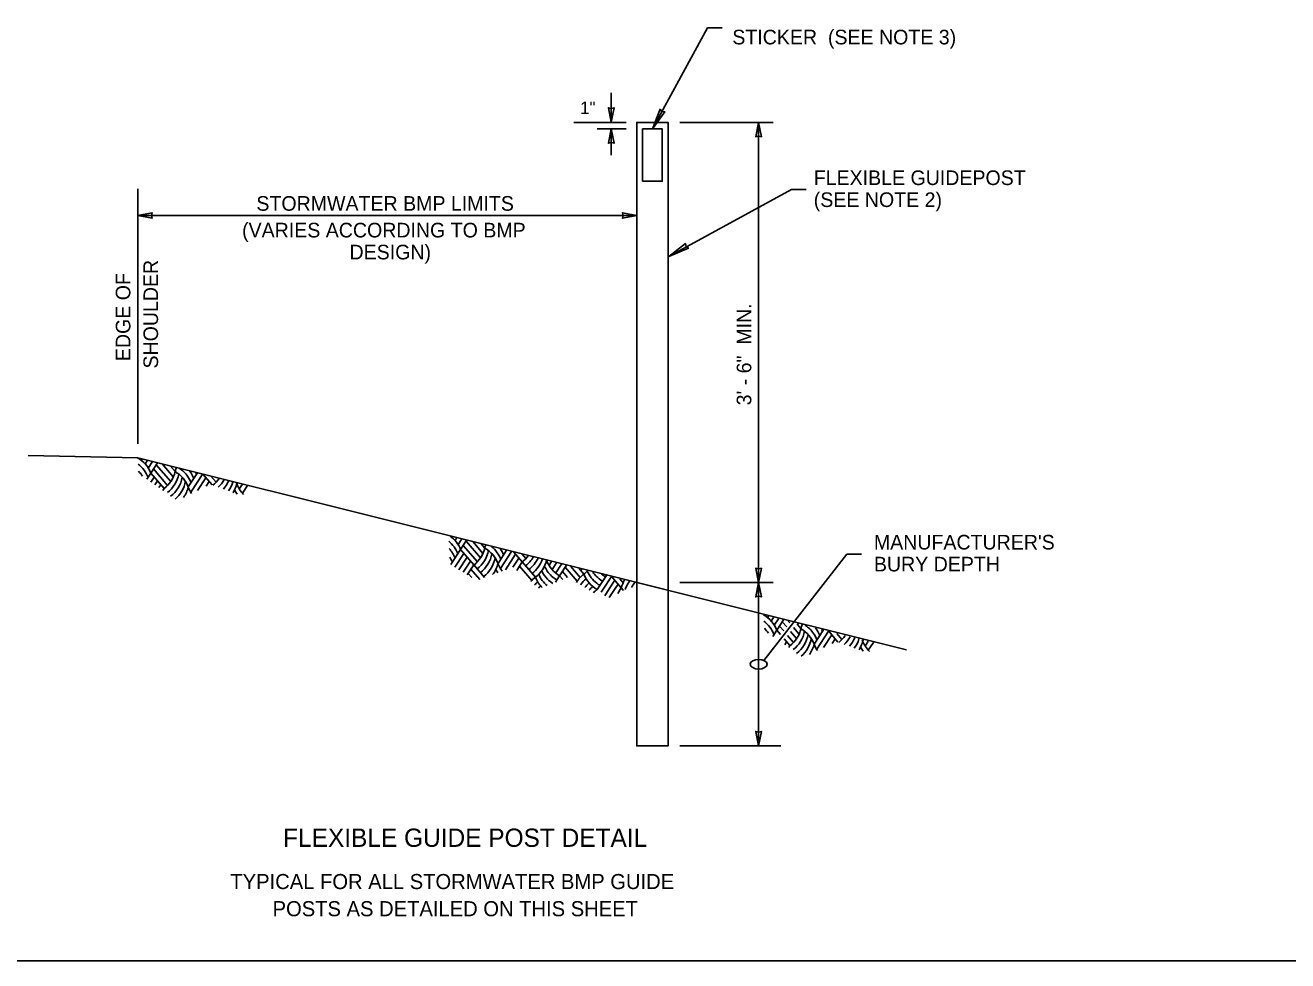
# Model space of a CAD drawing. Extents: x 99862 to 103151, y 100000 to 102076.
# Drawn here: x 101059 to 102440, y 100000 to 101023 of the extents above; entities that cross this region are included whole.
import ezdxf

# ---------------------------------------------------------------- set-up
doc = ezdxf.new("R2010")
doc.units = 0
for name, color, linetype in [('Default', 7, 'Continuous'), ('EV_EC_VegetativeFilterStripNew', 7, 'Continuous'), ('Level 1', 7, 'Continuous'), ('Level 13', 7, 'Continuous'), ('Level 15', 7, 'Continuous'), ('Level 20', 7, 'Continuous'), ('Level 5', 7, 'Continuous'), ('SH_DE_DetailLevel9', 7, 'Continuous')]:
    doc.layers.add(name, color=color, linetype=linetype)

msp = doc.modelspace()

# ---------------------------------------------------------------- linework, layer by layer
at = {"layer": 'Default'}
for p, q in [((101061.7, 100552.1), (101181.5, 100549.7)), ((101181.5, 100549.7), (101181.5, 100549.7)), ((101727.5, 100413.2), (101807.7, 100393.2)), ((101807.7, 100393.2), (102022.4, 100339.5))]:
    msp.add_line(p, q, dxfattribs=at)
at = {"layer": 'EV_EC_VegetativeFilterStripNew'}
msp.add_line((101181.5, 100549.7), (101757, 100405.9), dxfattribs=at)
at = {"layer": 'Level 1'}
msp.add_lwpolyline([(99862, 99999.5), (103151, 99999.5), (103151, 102075.5), (99862, 102075.5)], close=True, dxfattribs=at)
at = {"layer": 'Level 13'}
for p, q in [((101185.8, 100546.7), (101186.9, 100548.4)), ((101189.7, 100542.9), (101192.4, 100547)), ((101195.9, 100532.9), (101191.6, 100526.3)), ((101193.1, 100538.4), (101197.8, 100545.6)), ((101203.3, 100544.2), (101195.9, 100532.9)), ((101195.9, 100532.9), (101210.3, 100516.1)), ((101198.9, 100537.5), (101214.2, 100519.6)), ((101201.9, 100542.2), (101217.6, 100523.8)), ((101208.2, 100543), (101220.4, 100528.8)), ((101217.1, 100540.8), (101222.4, 100534.6)), ((101247, 100533.3), (101236.8, 100517.8)), ((101195.9, 100523.2), (101199.5, 100528.7)), ((101200.3, 100520.2), (101203.1, 100524.5)), ((101204.6, 100517.1), (101206.7, 100520.3)), ((101239.6, 100512.2), (101252.6, 100532.1)), ((101247, 100513.9), (101256.2, 100527.9)), ((101252.8, 100531.8), (101262.9, 100520)), ((101256.4, 100518.6), (101259.8, 100523.7)), ((101261.7, 100529.5), (101267.3, 100523)), ((101270.7, 100527.3), (101270.7, 100527.2)), ((101289.9, 100521.2), (101290.6, 100522.3)), ((101292.7, 100515.7), (101296.1, 100520.9)), ((101296, 100511.1), (101301.5, 100519.5)), ((101210.3, 100516.1), (101209, 100514.1)), ((101524.7, 100463.1), (101525, 100463.7)), ((101534.7, 100449.3), (101524, 100432.9)), ((101528.6, 100459.4), (101530.5, 100462.3)), ((101532, 100454.8), (101536, 100460.9)), ((101541.4, 100459.6), (101534.7, 100449.3)), ((101534.7, 100449.3), (101549.1, 100432.5)), ((101537.7, 100453.9), (101553.1, 100436)), ((101540.8, 100458.6), (101556.5, 100440.3)), ((101548.5, 100457.8), (101559.2, 100445.2)), ((101557.4, 100455.5), (101561.3, 100451)), ((101528.5, 100430.1), (101538.3, 100445.1)), ((101533, 100427.3), (101541.9, 100440.9)), ((101537.5, 100424.5), (101545.5, 100436.7)), ((101585.1, 100448.6), (101575.7, 100434.2)), ((101578.4, 100428.7), (101590.5, 100447.2)), ((101583.8, 100427.2), (101595, 100444.3)), ((101591.9, 100429.9), (101598.6, 100440.1)), ((101593.1, 100446.6), (101602.2, 100435.9)), ((101602.2, 100435.9), (101596.1, 100426.5)), ((101602, 100444.3), (101606.1, 100439.4)), ((101602.2, 100435.9), (101616.6, 100419)), ((101628.7, 100437.6), (101628.7, 100437.6)), ((101631.5, 100432.1), (101634.2, 100436.2)), ((101542.1, 100421.7), (101549.1, 100432.5)), ((101543.1, 100423.2), (101547, 100418.6)), ((101546.1, 100427.8), (101555.7, 100416.6)), ((101549.1, 100432.5), (101561, 100418.6)), ((101599.2, 100431.2), (101612.7, 100415.5)), ((101634.9, 100427.5), (101639.7, 100434.8)), ((101638.8, 100423.8), (101645.1, 100433.5)), ((101650.6, 100432.1), (101643.1, 100420.7)), ((101646.2, 100425.4), (101651.8, 100418.8)), ((101649.2, 100430), (101662.3, 100414.6)), ((101655.5, 100430.8), (101665.7, 100418.9)), ((101664.4, 100428.6), (101669.7, 100422.4)), ((101643.1, 100420.7), (101638.4, 100413.5)), ((101643.1, 100420.7), (101646.6, 100416.7)), ((101694.2, 100421.1), (101684.1, 100405.6)), ((101690.7, 100406), (101699.8, 100419.9)), ((101697.4, 100406.4), (101703.4, 100415.7)), ((101700.1, 100419.6), (101710.6, 100407.3)), ((101704, 100406.9), (101707, 100411.5)), ((101709, 100417.4), (101712.7, 100413.1)), ((101688.5, 100402.6), (101690.7, 100406)), ((101692.4, 100398.8), (101697.4, 100406.4)), ((101697.4, 100396.8), (101704, 100406.9)), ((101710.6, 100407.3), (101706.8, 100401.4)), ((101710.6, 100407.3), (101713, 100404.5)), ((101870.6, 100374.8), (101871.7, 100376.5)), ((101874.5, 100371.1), (101877.1, 100375.1)), ((101877.9, 100366.5), (101882.6, 100373.7)), ((101888, 100372.4), (101880.6, 100361)), ((101886.7, 100370.3), (101891.5, 100364.7)), ((101893, 100371.1), (101894.8, 100369)), ((101902.8, 100367.8), (101907.2, 100362.7)), ((101880.6, 100361), (101876.3, 100354.4)), ((101880.6, 100361), (101884.6, 100356.3)), ((101883.6, 100365.6), (101888.2, 100360.3)), ((101892.3, 100355.5), (101899, 100347.7)), ((101895.6, 100359.8), (101902.4, 100352)), ((101899.1, 100364), (101905.1, 100356.9)), ((101931.7, 100361.4), (101921.6, 100345.9)), ((101924.3, 100340.4), (101937.3, 100360.2)), ((101931.8, 100342.1), (101940.9, 100356)), ((101937.6, 100359.9), (101947.6, 100348.1)), ((101946.5, 100357.6), (101952, 100351.1)), ((101955.4, 100355.4), (101955.4, 100355.4)), ((101888.7, 100351.5), (101895, 100344.2)), ((101889.4, 100345.2), (101891.4, 100348.4)), ((101895, 100344.2), (101893.7, 100342.2)), ((101941.2, 100346.7), (101944.5, 100351.8)), ((101974.6, 100349.3), (101975.4, 100350.4)), ((101977.4, 100343.8), (101980.8, 100349)), ((101980.8, 100339.2), (101986.3, 100347.6))]:
    msp.add_line(p, q, dxfattribs=at)
for centre, start, end in [((101164.5, 100520.7), 21.3138, 59.7667), ((101161.5, 100516), 21.3138, 52.6301), ((101158.5, 100511.4), 32.9159, 44.6118), ((101189.8, 100542.7), 307.574, 346.0269), ((101251.5, 100530.7), 163.5014, 166.0269), ((101255.1, 100526.5), 158.0219, 166.0269), ((101205.5, 100505.5), 21.3138, 59.7667), ((101208.5, 100510.2), 35.002, 56.6803), ((101211.5, 100514.8), 21.3138, 37.946), ((101214.6, 100519.4), 21.3138, 25.1578), ((101193.4, 100538.5), 307.574, 348.6816), ((101197, 100534.3), 307.574, 349.9902), ((101200.6, 100530.1), 310.7187, 349.4417), ((101208.5, 100510.2), 21.3138, 35.0021), ((101242.8, 100546.1), 308.2655, 325.9231), ((101246.4, 100541.9), 313.5377, 331.6331), ((101250, 100537.7), 318.5798, 337.2018), ((101253.6, 100533.5), 323.4546, 342.6888), ((101257.2, 100529.3), 328.2102, 346.0269), ((101258.6, 100508.9), 21.3138, 23.9592), ((101321.3, 100533.4), 201.3139, 224.7347), ((101204.2, 100525.9), 324.3833, 346.0269), ((101268.2, 100530), 201.3139, 214.8748), ((101318.2, 100528.8), 204.5482, 214.0621), ((101503.4, 100437.1), 21.3138, 53.3766), ((101500.3, 100432.4), 21.3138, 50.5158), ((101497.3, 100427.8), 21.3138, 42.1564), ((101528.6, 100459.1), 307.574, 346.0269), ((101590.3, 100447.1), 165.613, 166.0269), ((101593.9, 100442.9), 160.1478, 166.0269), ((101544.3, 100421.9), 21.3138, 59.7667), ((101547.3, 100426.6), 35.002, 51.0452), ((101550.4, 100431.2), 21.3138, 34.6327), ((101494.3, 100423.2), 21.3138, 31.8403), ((101532.2, 100454.9), 307.574, 348.6816), ((101535.8, 100450.7), 307.574, 349.9902), ((101539.4, 100446.5), 307.574, 349.4417), ((101547.3, 100426.6), 21.3138, 35.0021), ((101553.4, 100435.8), 21.3138, 22.4807), ((101581.7, 100462.5), 307.574, 323.6606), ((101585.3, 100458.3), 307.574, 329.4442), ((101588.9, 100454.1), 307.574, 335.0599), ((101592.5, 100449.9), 307.574, 340.572), ((101596.1, 100445.7), 307.574, 346.0269), ((101597.4, 100425.3), 21.3138, 21.3238), ((101660.1, 100449.8), 201.3139, 239.7667), ((101543, 100442.3), 322.74, 346.0269), ((101604, 100441.8), 204.5482, 211.8304), ((101607, 100446.4), 201.3139, 217.591), ((101651, 100435.9), 203.9136, 230.4364), ((101654, 100440.5), 205.1047, 224.612), ((101657.1, 100445.2), 204.5482, 215.0023), ((101657.1, 100445.2), 215.0022, 239.7667), ((101690.2, 100395.8), 127.574, 148.4574), ((101645.6, 100453.3), 307.574, 310.7344), ((101649.2, 100449.1), 307.574, 317.1654), ((101701, 100434.7), 201.3138, 239.7667), ((101704.1, 100439.3), 203.9136, 232.6303), ((101707.1, 100443.9), 214.6079, 224.612), ((101710.1, 100448.6), 231.0063, 239.7667), ((101637.1, 100392.4), 127.574, 139.497), ((101640.7, 100388.1), 129.9766, 137.7179), ((101648, 100431.3), 201.3138, 224.3945), ((101644.3, 100383.9), 130.7709, 135.9353), ((101654, 100440.5), 224.6119, 236.8532), ((101693.8, 100391.6), 129.9766, 145.5562), ((101697.4, 100387.3), 130.7709, 142.6477), ((101701, 100383.1), 130.0013, 139.3831), ((101707.1, 100443.9), 224.6119, 239.7667), ((101704.1, 100439.3), 232.6302, 239.7667), ((101743.3, 100399.2), 149.8498, 166.0269), ((101746.9, 100395), 144.0807, 157.897), ((101750.5, 100390.7), 138.0682, 149.1614), ((101701, 100383.1), 139.383, 139.724), ((101704.6, 100378.9), 127.574, 136.7772), ((101746.9, 100395), 157.8969, 161.8589), ((101849.3, 100348.8), 21.3138, 59.7667), ((101846.2, 100344.1), 21.3138, 52.6301), ((101936.2, 100358.8), 163.5014, 166.0269), ((101939.8, 100354.6), 158.0219, 166.0269), ((101843.2, 100339.5), 32.9159, 44.6118), ((101874.5, 100370.8), 307.574, 346.0269), ((101878.1, 100366.6), 307.574, 348.6816), ((101881.7, 100362.4), 307.574, 349.9902), ((101890.2, 100333.6), 21.3138, 59.7667), ((101893.2, 100338.3), 35.002, 56.6803), ((101893.2, 100338.3), 21.3138, 35.0021), ((101896.3, 100342.9), 21.3138, 37.946), ((101899.3, 100347.5), 21.3138, 25.1578), ((101927.6, 100374.2), 308.2655, 325.9231), ((101931.2, 100370), 313.5377, 331.6331), ((101934.8, 100365.8), 318.5798, 337.2018), ((101885.3, 100358.2), 310.7187, 349.4417), ((101888.9, 100354), 324.3833, 346.0269), ((101952.9, 100358.1), 201.3139, 214.8748), ((101938.4, 100361.6), 323.4546, 342.6888), ((101942, 100357.4), 328.2102, 346.0269), ((102003, 100356.9), 204.5482, 214.0621), ((101943.3, 100337), 21.3138, 23.9592), ((102006, 100361.5), 201.3139, 224.7347)]:
    msp.add_arc(centre, 33.7, start, end, dxfattribs=at)
at = {"layer": 'Level 15'}
for p, q in [((101804.9, 101020.1), (101820.9, 101020.1)), ((101774.5, 100916.6), (101876.8, 100916.6)), ((101181.5, 100565), (101181.5, 100843.8)), ((101896.7, 100843.2), (101912.7, 100843.2)), ((101957.4, 100444.4), (101973.4, 100444.4)), ((101774.5, 100413.2), (101876.8, 100413.2)), ((101774.5, 100234.6), (101885.2, 100234.6))]:
    msp.add_line(p, q, dxfattribs=at)
for points in [[(101744.7, 100909.5), (101758.2, 100928.1), (101755, 100928.6), (101752.9, 100931)], [(101860.8, 100916.6), (101863.9, 100900.9), (101860.8, 100901.7), (101857.7, 100900.9)], [(101181.5, 100814.8), (101197.2, 100811.7), (101196.5, 100814.8), (101197.2, 100817.8)], [(101727.5, 100814.8), (101711.8, 100811.7), (101712.5, 100814.8), (101711.8, 100817.8)], [(101762.7, 100770.1), (101783.9, 100778.9), (101781.5, 100781), (101780.9, 100784.1)], [(101860.8, 100413.2), (101863.9, 100428.9), (101860.8, 100428.2), (101857.7, 100428.9)], [(101860.8, 100413.2), (101863.9, 100397.5), (101860.8, 100398.2), (101857.7, 100397.5)], [(101860.8, 100234.6), (101863.9, 100250.3), (101860.8, 100249.6), (101857.7, 100250.3)]]:
    msp.add_lwpolyline(points, close=True, dxfattribs=at)
msp.add_ellipse((101860.8, 100323.9), major_axis=(-9.21, 0), ratio=0.57735, dxfattribs=at)
at = {"layer": 'Level 5'}
for points in [[(101727.5, 100413.2), (101727.5, 100916.6), (101761.8, 100916.6), (101761.8, 100404.7)], [(101761.8, 100404.7), (101761.8, 100234.6), (101727.5, 100234.6), (101727.5, 100413.2)]]:
    msp.add_lwpolyline(points, dxfattribs=at)
at = {"layer": 'SH_DE_DetailLevel9'}
for p, q in [((101744.7, 100909.5), (101804.9, 101020.1)), ((101699.5, 100948.9), (101699.5, 100917)), ((101658.6, 100916.6), (101715.8, 100916.6)), ((101684.3, 100909.5), (101715.8, 100909.5)), ((101699.5, 100909.5), (101699.5, 100880.8)), ((101860.8, 100413.2), (101860.8, 100916.6)), ((101762.7, 100770.1), (101896.7, 100843.2)), ((101181.5, 100814.8), (101727.5, 100814.8)), ((101882.2, 100348.2), (101957.4, 100444.4)), ((101860.8, 100234.6), (101860.8, 100413.2)), ((101866.4, 100328.1), (101882.2, 100348.2))]:
    msp.add_line(p, q, dxfattribs=at)
for points in [[(101699.5, 100917), (101702.6, 100932.7), (101699.5, 100932), (101696.4, 100932.7)], [(101699.5, 100909.5), (101702.6, 100893.8), (101699.5, 100894.5), (101696.4, 100893.8)], [(101733.9, 100909.5), (101755.4, 100909.5), (101755.4, 100852.2), (101733.9, 100852.2)]]:
    msp.add_lwpolyline(points, close=True, dxfattribs=at)
msp.add_lwpolyline([(101733.9, 100909.5), (101733.9, 100852.2), (101755.4, 100852.2), (101755.4, 100909.5), (101744.7, 100909.5), (101733.9, 100909.5)], dxfattribs=at)

# ---------------------------------------------------------------- texts
at = {"layer": 'Level 20'}
for s, height, p in [('STICKER  (SEE NOTE 3)', 16, (101832, 101002)), ('FLEXIBLE GUIDEPOST ', 16, (101921.1, 100848.1)), ('(SEE NOTE 2)', 16, (101921.1, 100824.1)), ('(VARIES ACCORDING TO BMP', 16, (101295.7, 100790.8)), (' DESIGN)', 16, (101407.3, 100766.8)), ("MANUFACTURER'S ", 16, (101986.9, 100449.4)), ('BURY DEPTH', 16, (101986.9, 100425.4)), ('FLEXIBLE GUIDE POST DETAIL', 20, (101340.6, 100124.1)), ('TYPICAL FOR ALL STORMWATER BMP GUIDE ', 16.5, (101282.9, 100077.9)), ('POSTS AS DETAILED ON THIS SHEET', 16.5, (101329.1, 100048.2))]:
    msp.add_text(s, height=height, dxfattribs=at).set_placement(p)
for s, rotation, p in [('STORMWATER BMP LIMITS', 360, (101311.4, 100820)), ('SHOULDER', 90, (101203.8, 100647.4)), ('EDGE OF', 90, (101173.5, 100655.5)), ('3\' - 6"  MIN.', 90, (101852.8, 100607.1))]:
    msp.add_text(s, height=16, rotation=rotation, dxfattribs=at).set_placement(p)
at = {"layer": 'SH_DE_DetailLevel9'}
msp.add_text('1"', height=13.67, dxfattribs=at).set_placement((101665.6, 100925.8))

doc.saveas('drawing.dxf')
